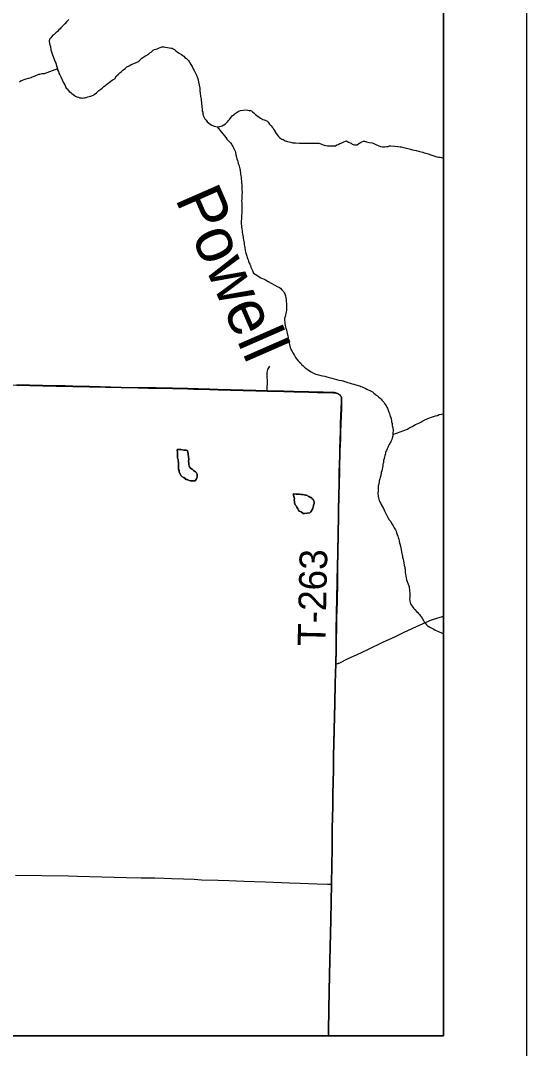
# Model space of a CAD drawing. Extents: x -483 to 680, y 0 to 440.
# Drawn here: x 342.2 to 394.1, y 54.6 to 160 of the extents above; entities that cross this region are included whole.
import ezdxf

# ---------------------------------------------------------------- set-up
doc = ezdxf.new("R2010")
doc.units = 0
for name, color, linetype in [('GM_X_County_Road', 7, 'Continuous'), ('GM_X_Minor_Lake', 7, 'Continuous'), ('GM_X_Minor_River', 7, 'Continuous'), ('GM_X_Minor_River_Text', 7, 'Continuous'), ('GM_X_Township_Road', 7, 'Continuous'), ('GM_X_Township_Road_Text', 7, 'Continuous'), ('SH_Cut_Line', 7, 'Continuous'), ('SH_Text', 7, 'Continuous')]:
    doc.layers.add(name, color=color, linetype=linetype)

msp = doc.modelspace()

# ---------------------------------------------------------------- linework, layer by layer
at = {"layer": 'GM_X_County_Road'}
for points in [[(374.55, 94.08), (374.68, 94.1), (374.78, 94.11), (374.84, 94.13), (374.89, 94.14), (374.96, 94.18), (375.81, 94.61), (376.66, 95), (377.82, 95.53), (379.39, 96.28), (380.68, 96.89), (381.58, 97.31), (382.84, 97.91), (383.81, 98.34), (384.38, 98.57), (384.91, 98.75), (385.5, 98.92), (385.61, 98.94)], [(374.12, 71.48), (374.16, 73.39), (374.18, 75.1), (374.2, 77.27), (374.23, 78.21), (374.25, 79.6), (374.27, 80.69), (374.32, 83.19), (374.35, 84.58), (374.47, 90.01), (374.5, 92.03), (374.55, 94.08)], [(341.68, 72.41), (347.13, 72.33), (348.06, 72.31), (353.07, 72.17), (354.58, 72.14), (355.98, 72.12), (356.91, 72.1), (357.69, 72.08), (358.93, 72.03), (360.01, 71.98), (360.78, 71.94), (362.49, 71.88), (363.58, 71.85), (365.14, 71.79), (366.22, 71.75), (367.31, 71.72), (369.8, 71.63), (370.89, 71.6), (372.6, 71.53), (373.69, 71.49), (374.12, 71.48)], [(373.81, 55.95), (373.82, 56.3), (373.86, 58.69), (373.93, 62.2), (374.04, 67.8), (374.12, 71.48)]]:
    msp.add_lwpolyline(points, dxfattribs=at)
at = {"layer": 'GM_X_Minor_Lake'}
for points in [[(358.29, 116.06), (358.32, 115.71), (358.32, 115.6), (358.32, 115.47), (358.32, 115.31), (358.33, 115.14), (358.37, 115.01), (358.39, 114.88), (358.41, 114.72), (358.42, 114.59), (358.42, 114.48), (358.42, 114.38), (358.42, 114.27), (358.42, 114.15), (358.43, 113.98), (358.47, 113.89), (358.49, 113.75), (358.56, 113.58), (358.69, 113.35), (358.79, 113.25), (358.96, 113.18), (359.09, 113.06), (359.18, 112.98), (359.3, 112.96), (359.43, 112.9), (359.6, 112.84), (360.11, 112.84), (360.19, 112.93), (360.25, 113.03), (360.31, 113.12)], [(360.31, 113.12), (360.33, 113.25), (360.33, 113.4), (360.33, 113.5), (360.26, 113.65), (360.16, 113.75), (360.05, 113.81), (359.96, 113.88), (359.82, 114.02), (359.65, 114.14), (359.56, 114.25), (359.5, 114.38), (359.47, 114.5), (359.47, 114.59), (359.45, 114.88), (359.46, 114.99), (359.46, 115.13), (359.44, 115.22), (359.44, 115.32), (359.42, 115.49), (359.41, 115.64), (359.39, 115.74), (359.35, 115.95), (359.2, 115.97), (359.09, 115.99), (358.97, 115.99), (358.65, 116.03), (358.29, 116.06), (358.29, 116.06)], [(358.29, 116.06), (358.29, 116.06), (358.65, 116.03), (358.97, 115.99), (359.09, 115.99), (359.2, 115.97), (359.35, 115.95), (359.39, 115.74), (359.41, 115.64), (359.42, 115.49), (359.44, 115.32), (359.44, 115.22), (359.46, 115.13), (359.46, 114.99), (359.45, 114.88), (359.47, 114.59), (359.47, 114.5), (359.5, 114.38), (359.56, 114.25), (359.65, 114.14), (359.82, 114.02), (359.96, 113.88), (360.05, 113.81), (360.16, 113.75), (360.26, 113.65), (360.33, 113.5), (360.33, 113.4), (360.33, 113.25), (360.31, 113.12), (360.25, 113.03), (360.19, 112.93), (360.11, 112.84), (359.6, 112.84), (359.43, 112.9), (359.3, 112.96), (359.18, 112.98), (359.09, 113.06), (358.96, 113.18), (358.79, 113.25), (358.69, 113.35), (358.56, 113.58), (358.49, 113.75), (358.47, 113.89), (358.43, 113.98), (358.42, 114.15), (358.42, 114.27), (358.42, 114.38), (358.42, 114.48), (358.42, 114.59), (358.41, 114.72), (358.39, 114.88), (358.37, 115.01), (358.33, 115.14), (358.32, 115.31), (358.32, 115.47), (358.32, 115.6), (358.32, 115.71), (358.29, 116.06)], [(372.28, 110.26), (372.28, 110.35), (372.32, 110.52), (372.32, 110.64), (372.3, 110.79), (372.23, 110.92), (372.13, 111), (372.06, 111.11), (371.96, 111.13), (371.77, 111.21), (371.55, 111.35), (371.43, 111.37), (371.3, 111.41), (371.15, 111.43), (371, 111.43), (370.83, 111.45), (370.71, 111.47), (370.47, 111.48), (370.2, 111.5), (370.18, 111.46)], [(370.18, 111.46), (370.2, 111.5), (370.47, 111.48), (370.71, 111.47), (370.83, 111.45), (371, 111.43), (371.15, 111.43), (371.3, 111.41), (371.43, 111.37), (371.55, 111.35), (371.77, 111.21), (371.96, 111.13), (372.06, 111.11), (372.13, 111), (372.23, 110.92), (372.3, 110.79), (372.32, 110.64), (372.32, 110.52), (372.28, 110.35), (372.28, 110.26), (372.24, 110.14), (372.2, 110.03), (372.16, 109.93), (372, 109.65), (371.89, 109.54), (371.34, 109.47), (371.2, 109.47), (370.99, 109.65), (370.81, 109.71), (370.73, 109.84), (370.64, 109.97), (370.54, 110.13), (370.47, 110.28), (370.4, 110.38), (370.36, 110.47), (370.32, 110.59), (370.3, 110.72), (370.29, 110.89), (370.33, 111.02), (370.18, 111.46)], [(370.18, 111.46), (370.33, 111.02), (370.29, 110.89), (370.3, 110.72), (370.32, 110.59), (370.36, 110.47), (370.4, 110.38), (370.47, 110.28), (370.54, 110.13), (370.64, 109.97), (370.73, 109.84), (370.81, 109.71), (370.99, 109.65), (371.2, 109.47), (371.34, 109.47), (371.89, 109.54), (372, 109.65), (372.16, 109.93), (372.2, 110.03), (372.24, 110.14), (372.28, 110.26)]]:
    msp.add_lwpolyline(points, dxfattribs=at)
at = {"layer": 'GM_X_Minor_River'}
for points in [[(347.16, 160.13), (346.95, 159.93), (346.75, 159.68), (346.56, 159.46), (346.44, 159.38), (346.36, 159.27), (346.27, 159.18), (346.15, 159.05), (346.01, 158.9), (345.82, 158.75), (345.66, 158.6), (345.51, 158.51), (345.39, 158.36), (345.31, 158.25), (345.2, 158.1), (345.15, 157.95), (345.19, 157.64), (345.27, 157.34), (345.33, 157.03), (345.38, 156.82), (345.41, 156.69), (345.47, 156.55), (345.52, 156.44), (345.59, 156.22), (345.7, 155.94), (345.83, 155.65), (345.92, 155.28), (345.99, 155.05), (346.02, 154.96), (346.1, 154.8), (346.15, 154.63), (346.24, 154.44), (346.33, 154.25), (346.62, 153.63), (346.75, 153.44), (346.83, 153.27), (346.9, 153.09), (346.99, 153), (347.2, 152.76), (347.36, 152.64), (347.48, 152.55), (347.61, 152.43), (347.74, 152.35), (347.85, 152.27), (347.98, 152.21), (348.15, 152.15), (348.29, 152.11), (348.44, 152.09), (348.55, 152.07), (348.7, 152.08), (348.8, 152.1), (348.95, 152.13), (349.11, 152.19), (349.26, 152.22), (349.39, 152.26), (349.49, 152.29), (349.58, 152.33), (349.68, 152.38)], [(349.68, 152.38), (349.78, 152.44), (349.99, 152.61), (350.11, 152.72), (350.26, 152.85), (350.44, 152.98), (350.59, 153.09), (350.75, 153.24), (350.92, 153.35), (351.04, 153.46), (351.17, 153.55), (351.35, 153.7), (351.48, 153.79), (351.62, 153.9), (351.73, 153.98), (351.87, 154.05), (352.07, 154.35), (352.26, 154.53), (352.41, 154.65), (352.55, 154.76), (352.71, 154.92), (352.8, 155), (352.96, 155.09), (353.13, 155.26), (353.34, 155.39), (353.56, 155.5), (353.84, 155.62), (354.07, 155.73), (354.25, 155.8), (354.36, 155.86), (354.52, 156.01), (354.66, 156.16), (354.85, 156.29), (355.02, 156.41), (355.16, 156.47), (355.29, 156.54), (355.49, 156.71), (355.6, 156.78), (355.72, 156.88), (355.83, 156.97), (355.97, 157.04), (356.08, 157.08), (356.22, 157.13), (356.37, 157.2), (356.54, 157.26), (356.72, 157.31), (356.81, 157.31), (356.93, 157.31), (357.08, 157.28), (357.69, 157.19), (357.78, 157.17), (357.87, 157.11), (357.99, 157.05), (358.1, 156.96), (358.27, 156.82), (358.47, 156.66), (358.72, 156.52), (358.87, 156.44), (358.96, 156.37), (359.07, 156.23), (359.22, 156.13), (359.34, 156.01), (359.43, 155.92), (359.5, 155.82), (359.58, 155.69), (359.69, 155.51), (359.82, 155.3), (359.92, 155.07), (360.05, 154.84), (360.16, 154.63), (360.27, 154.43), (360.36, 154.16), (360.42, 153.95), (360.47, 153.69), (360.52, 153.4), (360.59, 153.09), (360.62, 152.83), (360.65, 152.54), (360.68, 152.27), (360.72, 152.1), (360.73, 151.97), (360.75, 151.8), (360.77, 151.62), (360.78, 151.49), (360.8, 151.32), (360.81, 151.13), (360.83, 150.92), (360.84, 150.82), (360.86, 150.73), (360.9, 150.61), (360.91, 150.44), (360.96, 150.27), (361.02, 150.13), (361.13, 149.94), (361.26, 149.79), (361.37, 149.65), (361.67, 149.41), (361.84, 149.3), (362.08, 149.2), (362.24, 149.15), (362.39, 149.11)], [(345.99, 155.05), (344.62, 154.55), (344.38, 154.54), (344.17, 154.5), (344.05, 154.47), (343.92, 154.42), (343.76, 154.34), (343.67, 154.31), (343.57, 154.27), (343.42, 154.22), (343.3, 154.16), (343.15, 154.11), (342.98, 154.06), (342.77, 154), (342.54, 153.93), (342.38, 153.88), (342.29, 153.82), (342.11, 153.71)], [(362.39, 149.11), (362.52, 149.11), (362.67, 149.15), (362.9, 149.24), (363.06, 149.31), (363.23, 149.44), (363.33, 149.53), (363.45, 149.64), (363.54, 149.77), (363.66, 149.87), (363.72, 149.96), (363.86, 150.13), (363.95, 150.28), (364.11, 150.39), (364.22, 150.48), (364.32, 150.57), (364.42, 150.63), (364.55, 150.7), (364.78, 150.79), (365.05, 150.84), (365.38, 150.86), (365.66, 150.81), (365.81, 150.79), (365.91, 150.77), (366.02, 150.65), (366.17, 150.53), (366.32, 150.4), (366.82, 150.02), (366.97, 149.94), (367.07, 149.88), (367.2, 149.84), (367.29, 149.8), (367.46, 149.72), (367.61, 149.59), (367.74, 149.41), (367.91, 149.24), (368.04, 149.1), (368.12, 148.99), (368.17, 148.87), (368.24, 148.77), (368.34, 148.6), (368.43, 148.43), (368.56, 148.25), (368.69, 148.12), (368.78, 148.02), (368.91, 147.94), (369.02, 147.86), (369.16, 147.82), (369.25, 147.76), (369.36, 147.7), (369.48, 147.66), (369.59, 147.62), (369.76, 147.58), (369.93, 147.54), (370.14, 147.49), (370.42, 147.47), (370.82, 147.46), (371.19, 147.43), (371.51, 147.44), (371.72, 147.44), (371.99, 147.43), (372.19, 147.45), (372.42, 147.44), (372.59, 147.44), (372.8, 147.44), (372.92, 147.41), (373.03, 147.37), (373.16, 147.31), (373.35, 147.25), (373.71, 147.17), (373.9, 147.16), (374.17, 147.16), (374.38, 147.17), (374.53, 147.19), (374.65, 147.26), (374.78, 147.32), (374.95, 147.41), (375.11, 147.46), (375.24, 147.51), (375.38, 147.57), (375.55, 147.66), (375.66, 147.68), (375.85, 147.56), (376.02, 147.48), (376.12, 147.44), (376.23, 147.36), (376.34, 147.3), (376.44, 147.28), (376.65, 147.27), (376.74, 147.27), (376.9, 147.4), (376.99, 147.46), (377.09, 147.51), (377.22, 147.58), (377.38, 147.64), (377.51, 147.65), (377.7, 147.59), (377.98, 147.53), (378.27, 147.47), (378.44, 147.42), (378.53, 147.38)], [(362.39, 149.11), (363.28, 148.03), (363.39, 147.85), (363.48, 147.76), (363.57, 147.64), (363.69, 147.56), (363.74, 147.47), (363.87, 147.31), (363.93, 147.21), (363.98, 147.12), (364.04, 147.02), (364.09, 146.89), (364.16, 146.75), (364.22, 146.62), (364.27, 146.48), (364.31, 146.25), (364.36, 146.02), (364.41, 145.85), (364.46, 145.68), (364.5, 145.53), (364.55, 145.37), (364.61, 145.24), (364.64, 145.1), (364.68, 144.95), (364.71, 144.82), (364.73, 144.72), (364.75, 144.57), (364.76, 144.42), (364.78, 144.26), (364.81, 144.11), (364.83, 143.96), (364.84, 143.79), (364.88, 143.59), (364.89, 143.4), (364.91, 143.19), (364.92, 143.02), (364.92, 142.85), (364.91, 142.64), (364.93, 142.38), (364.92, 142.15), (364.92, 141.92), (364.91, 141.71), (364.89, 141.54), (364.91, 141.39), (364.92, 141.21), (364.92, 141.01), (364.91, 140.76), (364.91, 140.57), (364.92, 140.4), (364.89, 139.94), (364.87, 139.81), (364.87, 139.67), (364.85, 139.52), (364.86, 139.43), (364.86, 139.29), (364.86, 139.16), (364.87, 138.99), (364.89, 138.84), (364.9, 138.65), (364.94, 138.45), (364.95, 138.28), (364.99, 138.15), (365, 137.98), (365.04, 137.8), (365.06, 137.67), (365.09, 137.52), (365.11, 137.35), (365.14, 137.19), (365.16, 137.08), (365.19, 136.87), (365.21, 136.77), (365.22, 136.68), (365.24, 136.54), (365.26, 136.43), (365.29, 136.31), (365.33, 136.18), (365.35, 136.08), (365.38, 135.97), (365.42, 135.85), (365.45, 135.74), (365.51, 135.61), (365.56, 135.47), (365.61, 135.34), (365.67, 135.16), (365.72, 135.03), (365.8, 134.89), (365.85, 134.72), (365.92, 134.59), (365.99, 134.41), (366.05, 134.28), (366.12, 134.13), (366.27, 134.01), (366.85, 133.65), (367.04, 133.57), (367.19, 133.49), (367.34, 133.43), (367.61, 133.27), (367.93, 133.08), (368.29, 132.9), (368.55, 132.76), (368.76, 132.66)], [(378.53, 147.38), (378.67, 147.3), (378.89, 147.22), (379.14, 147.12), (379.33, 147.08), (379.44, 147.06), (379.57, 147.06), (379.75, 147.09), (379.92, 147.12), (380.07, 147.16), (380.19, 147.19), (380.62, 147.15), (380.93, 147.12), (381.15, 147.08), (381.27, 147.08), (381.36, 147.05), (381.48, 147.01), (381.67, 146.97), (381.93, 146.91), (382.2, 146.83), (382.42, 146.78), (382.63, 146.74), (382.78, 146.68), (383.03, 146.64), (383.18, 146.6), (383.31, 146.55), (383.47, 146.53), (383.62, 146.47), (383.79, 146.43), (384.03, 146.35), (384.3, 146.25), (384.62, 146.14), (384.9, 146.06), (385.11, 146.02), (385.24, 146.02), (385.38, 145.98), (385.49, 145.95), (385.61, 145.94)], [(368.76, 132.66), (368.89, 132.58), (369.02, 132.42), (369.17, 132.23), (369.24, 132.12), (369.31, 132), (369.38, 131.79), (369.42, 131.6), (369.45, 131.43), (369.47, 131.23), (369.48, 131.01), (369.5, 130.8), (369.51, 130.61), (369.49, 130.43), (369.49, 130.28), (369.46, 130.15), (369.42, 129.98), (369.4, 129.85), (369.38, 129.73), (369.34, 129.58), (369.3, 129.49), (369.29, 129.28), (369.31, 129.14), (369.33, 129.01), (369.36, 128.74), (369.43, 128.48), (369.5, 128.28), (369.53, 128.11), (369.57, 127.98), (369.6, 127.81), (369.64, 127.69), (369.66, 127.56), (369.67, 127.42), (369.69, 127.27), (369.7, 127.1), (369.76, 126.96), (369.88, 126.5), (369.95, 126.35), (370.01, 126.2), (370.08, 126.08), (370.14, 125.97), (370.21, 125.85), (370.3, 125.68), (370.43, 125.48), (370.56, 125.31), (370.69, 125.12), (370.84, 125), (370.95, 124.88), (371.04, 124.77), (371.16, 124.67), (371.27, 124.55), (371.4, 124.43), (371.51, 124.36), (371.6, 124.28), (371.72, 124.2), (371.87, 124.1), (372.04, 124.02), (372.26, 123.88), (372.49, 123.78), (372.77, 123.7), (373.02, 123.64), (373.19, 123.59), (373.42, 123.55), (373.62, 123.49), (373.87, 123.43), (374.13, 123.35), (374.38, 123.28), (374.63, 123.22), (374.87, 123.16), (375.16, 123.11), (375.37, 123.05), (375.59, 122.97), (375.8, 122.91), (376.01, 122.85), (376.22, 122.79), (376.39, 122.74), (376.5, 122.72), (376.61, 122.68), (376.75, 122.64), (376.86, 122.6), (377.01, 122.56), (377.11, 122.5), (377.24, 122.46), (377.39, 122.4), (377.58, 122.32), (377.75, 122.24), (378.18, 122.04), (378.31, 121.94), (378.46, 121.82), (378.61, 121.67), (378.84, 121.53), (378.97, 121.41), (379.1, 121.31), (379.19, 121.22), (379.28, 121.1), (379.4, 120.98), (379.49, 120.89), (379.56, 120.75), (379.65, 120.61), (379.73, 120.52), (379.78, 120.4)], [(379.78, 120.4), (379.86, 120.29), (379.91, 120.06), (380, 119.88), (380.05, 119.73), (380.09, 119.6), (380.14, 119.44), (380.18, 119.33), (380.23, 119.16), (380.25, 119.02), (380.28, 118.87), (380.32, 118.72), (380.33, 118.58), (380.35, 118.49), (380.37, 118.39), (380.4, 118.22), (380.42, 118.07), (380.42, 117.95), (380.41, 117.74), (380.41, 117.59), (380.41, 117.46), (380.34, 117.19), (380.3, 117.08), (380.22, 116.93), (380.18, 116.83), (380.14, 116.74), (380.08, 116.65), (380.02, 116.55), (379.96, 116.42), (379.9, 116.25), (379.82, 116.1), (379.75, 115.95), (379.7, 115.84), (379.66, 115.74), (379.64, 115.59), (379.58, 115.44), (379.54, 115.29), (379.52, 115.12), (379.46, 114.91), (379.43, 114.68), (379.39, 114.53), (379.37, 114.38), (379.33, 114.21), (379.3, 114.02), (379.26, 113.85), (379.22, 113.68), (379.18, 113.37), (379.11, 113.17), (379.07, 113.05), (379.05, 112.94), (379.01, 112.83), (378.99, 112.73), (378.95, 112.56), (378.93, 112.39), (378.91, 112.29), (378.9, 112.12), (378.9, 111.97), (378.89, 111.76), (378.87, 111.61), (378.87, 111.46), (378.88, 111.34), (378.9, 111.25), (378.92, 111.1), (378.97, 110.96), (379.01, 110.83), (379.08, 110.67), (379.13, 110.58), (379.21, 110.4), (379.43, 109.98), (379.54, 109.75), (379.65, 109.54), (379.77, 109.29), (379.9, 109.06), (380.03, 108.84), (380.18, 108.65), (380.31, 108.44), (380.44, 108.23), (380.55, 108.01), (380.66, 107.8), (380.73, 107.67), (380.78, 107.51), (380.86, 107.34), (380.91, 107.17), (380.96, 107.01), (381, 106.84), (381.05, 106.63), (381.1, 106.48), (381.16, 106.27), (381.21, 105.98), (381.26, 105.77), (381.29, 105.56), (381.33, 105.39), (381.36, 105.25), (381.38, 105.16), (381.41, 104.99), (381.45, 104.8), (381.5, 104.58), (381.53, 104.41), (381.57, 104.16), (381.62, 103.99), (381.64, 103.88)], [(380.41, 117.59), (381.91, 118.13), (382.04, 118.22), (382.19, 118.29), (382.37, 118.4), (382.54, 118.49), (382.71, 118.59), (382.89, 118.68), (383.08, 118.75), (383.27, 118.86), (383.48, 118.97), (383.7, 119.08), (383.98, 119.21), (384.18, 119.3), (384.37, 119.37), (384.58, 119.44), (384.77, 119.49), (384.98, 119.54), (385.17, 119.62), (385.38, 119.67), (385.52, 119.7), (385.61, 119.73)], [(381.64, 103.88), (381.65, 103.76), (381.65, 103.67), (381.65, 103.57), (381.67, 103.42), (381.7, 103.25), (381.73, 103.06), (381.77, 102.9), (381.82, 102.69), (381.87, 102.52), (381.96, 102.25), (382.04, 102.08), (382.07, 101.98), (382.09, 101.83), (382.1, 101.68), (382.1, 101.58), (382.13, 101.3), (382.13, 101.14), (382.13, 101.05), (382.13, 100.92), (382.12, 100.75), (382.14, 100.61), (382.15, 100.5), (382.19, 100.36), (382.23, 100.23), (382.28, 100.11), (382.37, 100), (382.47, 99.88), (382.56, 99.75), (382.67, 99.63), (382.84, 99.45), (382.95, 99.34), (383.02, 99.22), (383.13, 99.12), (383.21, 99.03), (383.3, 98.89), (383.41, 98.74), (383.54, 98.51), (383.65, 98.31), (383.74, 98.2), (383.85, 98.06), (383.95, 97.98), (384.04, 97.92), (384.21, 97.82), (384.32, 97.75), (384.46, 97.69), (384.61, 97.61), (384.76, 97.53), (384.93, 97.45), (385.08, 97.37), (385.23, 97.31), (385.34, 97.27), (385.45, 97.23), (385.59, 97.15), (385.61, 97.13)]]:
    msp.add_lwpolyline(points, dxfattribs=at)
at = {"layer": 'GM_X_Township_Road'}
for points in [[(367.51, 122.04), (367.52, 122.37), (367.53, 122.87), (367.51, 123.69), (367.51, 123.93), (367.54, 124.09), (367.59, 124.23), (367.67, 124.4), (367.8, 124.6)], [(324.67, 123.07), (328.16, 122.98), (332.05, 122.88), (337.17, 122.75), (339.5, 122.7), (341.83, 122.65), (344.47, 122.58), (345.87, 122.55), (346.79, 122.53), (347.58, 122.51), (349.29, 122.47), (352.55, 122.39), (354.26, 122.35), (355.34, 122.34), (356.12, 122.33), (357.83, 122.29), (358.29, 122.29), (359.38, 122.27), (359.98, 122.24), (360.46, 122.23), (361.61, 122.19), (362.48, 122.17), (366.36, 122.07), (367.51, 122.04)], [(367.51, 122.04), (368.22, 122.02), (369.23, 121.98), (369.47, 121.98), (370.24, 121.96), (371.17, 121.94), (371.79, 121.92), (372.67, 121.9), (373.27, 121.89), (373.78, 121.87), (374.28, 121.86), (374.43, 121.85), (374.58, 121.82), (374.73, 121.77), (374.87, 121.7), (374.95, 121.64), (375.02, 121.56)], [(375.02, 121.56), (375.08, 121.47), (375.13, 121.34), (375.15, 121.19), (375.15, 120.88), (375.13, 120.2), (375.06, 118.7), (375.04, 117.77), (375.02, 117.15), (374.98, 115.91), (374.96, 115.34), (374.94, 114.67), (374.92, 113.58), (374.92, 113.53)], [(374.92, 113.53), (374.9, 112.81), (374.86, 111.09), (374.84, 109.95), (374.83, 109.23), (374.77, 105.5), (374.74, 103.94), (374.71, 102.7), (374.71, 102.39)], [(374.71, 102.39), (374.68, 100.52), (374.65, 99.43), (374.64, 98.96), (374.62, 97.72), (374.61, 97.58), (374.6, 96.63), (374.59, 95.54), (374.55, 94.08)], [(374.12, 71.48), (374.16, 73.39), (374.18, 75.1), (374.2, 77.27), (374.23, 78.21), (374.25, 79.6), (374.27, 80.69), (374.32, 83.19), (374.35, 84.58), (374.47, 90.01), (374.5, 92.03), (374.55, 94.08)], [(373.81, 55.95), (373.82, 56.3), (373.86, 58.69), (373.93, 62.2), (374.04, 67.8), (374.12, 71.48)]]:
    msp.add_lwpolyline(points, dxfattribs=at)
at = {"layer": 'SH_Cut_Line'}
for points in [[(341.82, 122.68), (344.46, 122.61), (345.86, 122.57), (346.78, 122.56), (347.57, 122.54), (349.27, 122.49), (352.53, 122.41), (354.24, 122.38), (355.33, 122.36), (356.11, 122.35), (357.81, 122.32), (358.28, 122.31), (359.36, 122.29), (359.97, 122.27), (360.45, 122.26), (361.59, 122.22), (362.47, 122.2), (366.35, 122.1), (367.5, 122.07), (368.21, 122.04), (369.21, 122.01), (369.45, 122), (370.23, 121.99), (371.16, 121.97), (371.78, 121.95), (372.66, 121.93), (373.26, 121.91), (373.77, 121.9), (374.27, 121.89), (374.42, 121.87), (374.57, 121.84), (374.72, 121.8), (374.85, 121.73), (374.94, 121.66), (375.01, 121.59), (375.07, 121.5), (375.12, 121.37), (375.14, 121.21), (375.14, 120.91), (375.11, 120.23), (375.05, 118.73), (375.03, 117.8), (375.01, 117.18), (374.96, 115.94), (374.95, 115.36), (374.93, 114.69), (374.91, 113.61), (374.89, 112.83), (374.85, 111.12), (374.83, 109.98), (374.82, 109.26), (374.76, 105.52), (374.73, 103.97), (374.7, 102.72), (374.67, 100.55), (374.64, 99.45), (374.63, 98.99), (374.6, 97.75), (374.6, 97.61), (374.59, 96.66), (374.58, 95.57), (374.54, 94.11), (374.49, 92.06), (374.45, 90.04), (374.33, 84.6), (374.31, 83.22), (374.26, 80.72), (374.24, 79.63), (374.21, 78.23), (374.19, 77.3), (374.17, 75.13), (374.15, 73.42), (374.11, 71.51), (374.03, 67.83), (373.92, 62.23), (373.85, 58.72), (373.8, 56.33), (373.8, 55.95), (385.61, 55.95), (385.61, 395.95)], [(45.61, 55.95), (373.8, 55.95), (373.8, 56.33), (373.85, 58.72), (373.92, 62.23), (374.03, 67.83), (374.11, 71.51), (374.15, 73.42), (374.17, 75.13), (374.19, 77.3), (374.21, 78.23), (374.24, 79.63), (374.26, 80.72), (374.31, 83.22), (374.33, 84.6), (374.45, 90.04), (374.49, 92.06), (374.54, 94.11), (374.58, 95.57), (374.59, 96.66), (374.6, 97.61), (374.6, 97.75), (374.63, 98.99), (374.64, 99.45), (374.67, 100.55), (374.7, 102.72), (374.73, 103.97), (374.76, 105.52), (374.82, 109.26), (374.83, 109.98), (374.85, 111.12), (374.89, 112.83), (374.91, 113.61), (374.93, 114.69), (374.95, 115.36), (374.96, 115.94), (375.01, 117.18), (375.03, 117.8), (375.05, 118.73), (375.11, 120.23), (375.14, 120.91), (375.14, 121.21), (375.12, 121.37), (375.07, 121.5), (375.01, 121.59), (374.94, 121.66), (374.85, 121.73), (374.72, 121.8), (374.57, 121.84), (374.42, 121.87), (374.27, 121.89), (373.77, 121.9), (373.26, 121.91), (372.66, 121.93), (371.78, 121.95), (371.16, 121.97), (370.23, 121.99), (369.45, 122), (369.21, 122.01), (368.21, 122.04), (367.5, 122.07), (366.35, 122.1), (362.47, 122.2), (361.59, 122.22), (360.45, 122.26), (359.97, 122.27), (359.36, 122.29), (358.28, 122.31), (357.81, 122.32), (356.11, 122.35), (355.33, 122.36), (354.24, 122.38), (352.53, 122.41), (349.27, 122.49), (347.57, 122.54), (346.78, 122.56), (345.86, 122.57), (344.46, 122.61), (341.82, 122.68)]]:
    msp.add_lwpolyline(points, dxfattribs=at)
at = {"layer": 'SH_Text'}
for points in [[(37.11, 404.45), (394.11, 404.45), (394.11, 47.45), (37.11, 47.45)], [(45.61, 395.95), (385.61, 395.95), (385.61, 55.95), (45.61, 55.95)]]:
    msp.add_lwpolyline(points, close=True, dxfattribs=at)

# ---------------------------------------------------------------- texts
at = {"layer": 'GM_X_Minor_River_Text'}
msp.add_text('Powell', height=4.738, rotation=293.6161, dxfattribs=at).set_placement((358.03, 141.77))
at = {"layer": 'GM_X_Township_Road_Text'}
msp.add_text('T-263', height=2.841, rotation=88.7043, dxfattribs=at).set_placement((373.47, 95.87))

doc.saveas('drawing.dxf')
